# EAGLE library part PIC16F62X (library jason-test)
MICROCONTROLLER EPROM/ROM-based
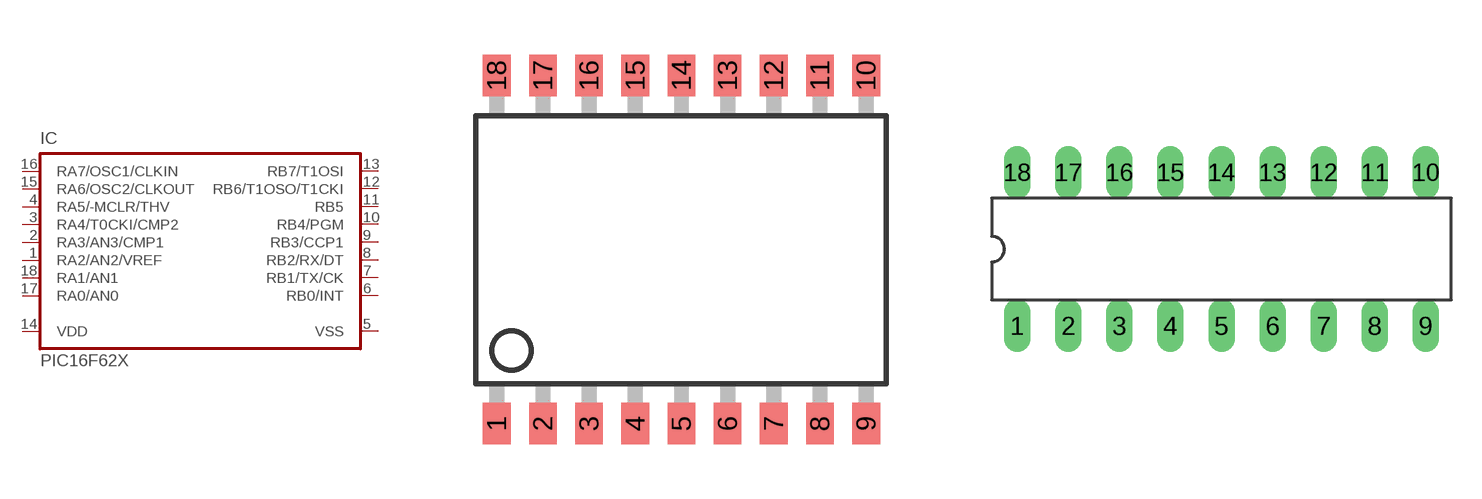
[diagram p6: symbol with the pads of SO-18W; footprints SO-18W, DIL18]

Designator prefix IC

## PIC16F62XSO  [SO-18W]
1  RA2/AN2/VREF
2  RA3/AN3/CMP1
3  RA4/T0CKI/CMP2
4  RA5/-MCLR/THV
5  VSS  pwr
6  RB0/INT
7  RB1/TX/CK
8  RB2/RX/DT
9  RB3/CCP1
10  RB4/PGM
11  RB5
12  RB6/T1OSO/T1CKI
13  RB7/T1OSI
14  VDD  pwr
15  RA6/OSC2/CLKOUT
16  RA7/OSC1/CLKIN
17  RA0/AN0
18  RA1/AN1

## PIC16F62XP  [DIL18]
Pads as for SO-18W

## PIC16F62XFP  [DIL18-F]
Pads as for SO-18W

## Footprint SO-18W (pad centres in mm)
Small Outline Wide Plastic Gull Wing 300-mil body, package type SO
smd 0.762 x 1.143: 1 -5.08,-4.788; 2 -3.81,-4.788; 3 -2.54,-4.788; 4 -1.27,-4.788; 5 0,-4.788; 6 1.27,-4.788; 7 2.54,-4.788; 8 3.81,-4.788; 9 5.08,-4.788; 10 5.08,4.788; 11 3.81,4.788; 12 2.54,4.788; 13 1.27,4.788; 14 0,4.788; 15 -1.27,4.788; 16 -2.54,4.788; 17 -3.81,4.788; 18 -5.08,4.788

## Footprint DIL18 (pad centres in mm)
Dual In Line package type P
drill 0.813 long: 1 -10.16,-3.81; 2 -7.62,-3.81; 3 -5.08,-3.81; 4 -2.54,-3.81; 5 0,-3.81; 6 2.54,-3.81; 7 5.08,-3.81; 8 7.62,-3.81; 9 10.16,-3.81; 10 10.16,3.81; 11 7.62,3.81; 12 5.08,3.81; 13 2.54,3.81; 14 0,3.81; 15 -2.54,3.81; 16 -5.08,3.81; 17 -7.62,3.81; 18 -10.16,3.81

## Footprint DIL18-F (pad centres in mm)
smd 3.81 x 1.016: 1 -5.08,0; 2 -5.08,-2.54; 3 -5.08,-5.08; 4 -5.08,-7.62; 5 -5.08,-10.16; 6 -5.08,-12.7; 7 -5.08,-15.24; 8 -5.08,-17.78; 9 -5.08,-20.32; 10 5.08,-20.32; 11 5.08,-17.78; 12 5.08,-15.24; 13 5.08,-12.7; 14 5.08,-10.16; 15 5.08,-7.62; 16 5.08,-5.08; 17 5.08,-2.54; 18 5.08,0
